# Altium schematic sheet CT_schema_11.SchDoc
size 564 x 458 mm
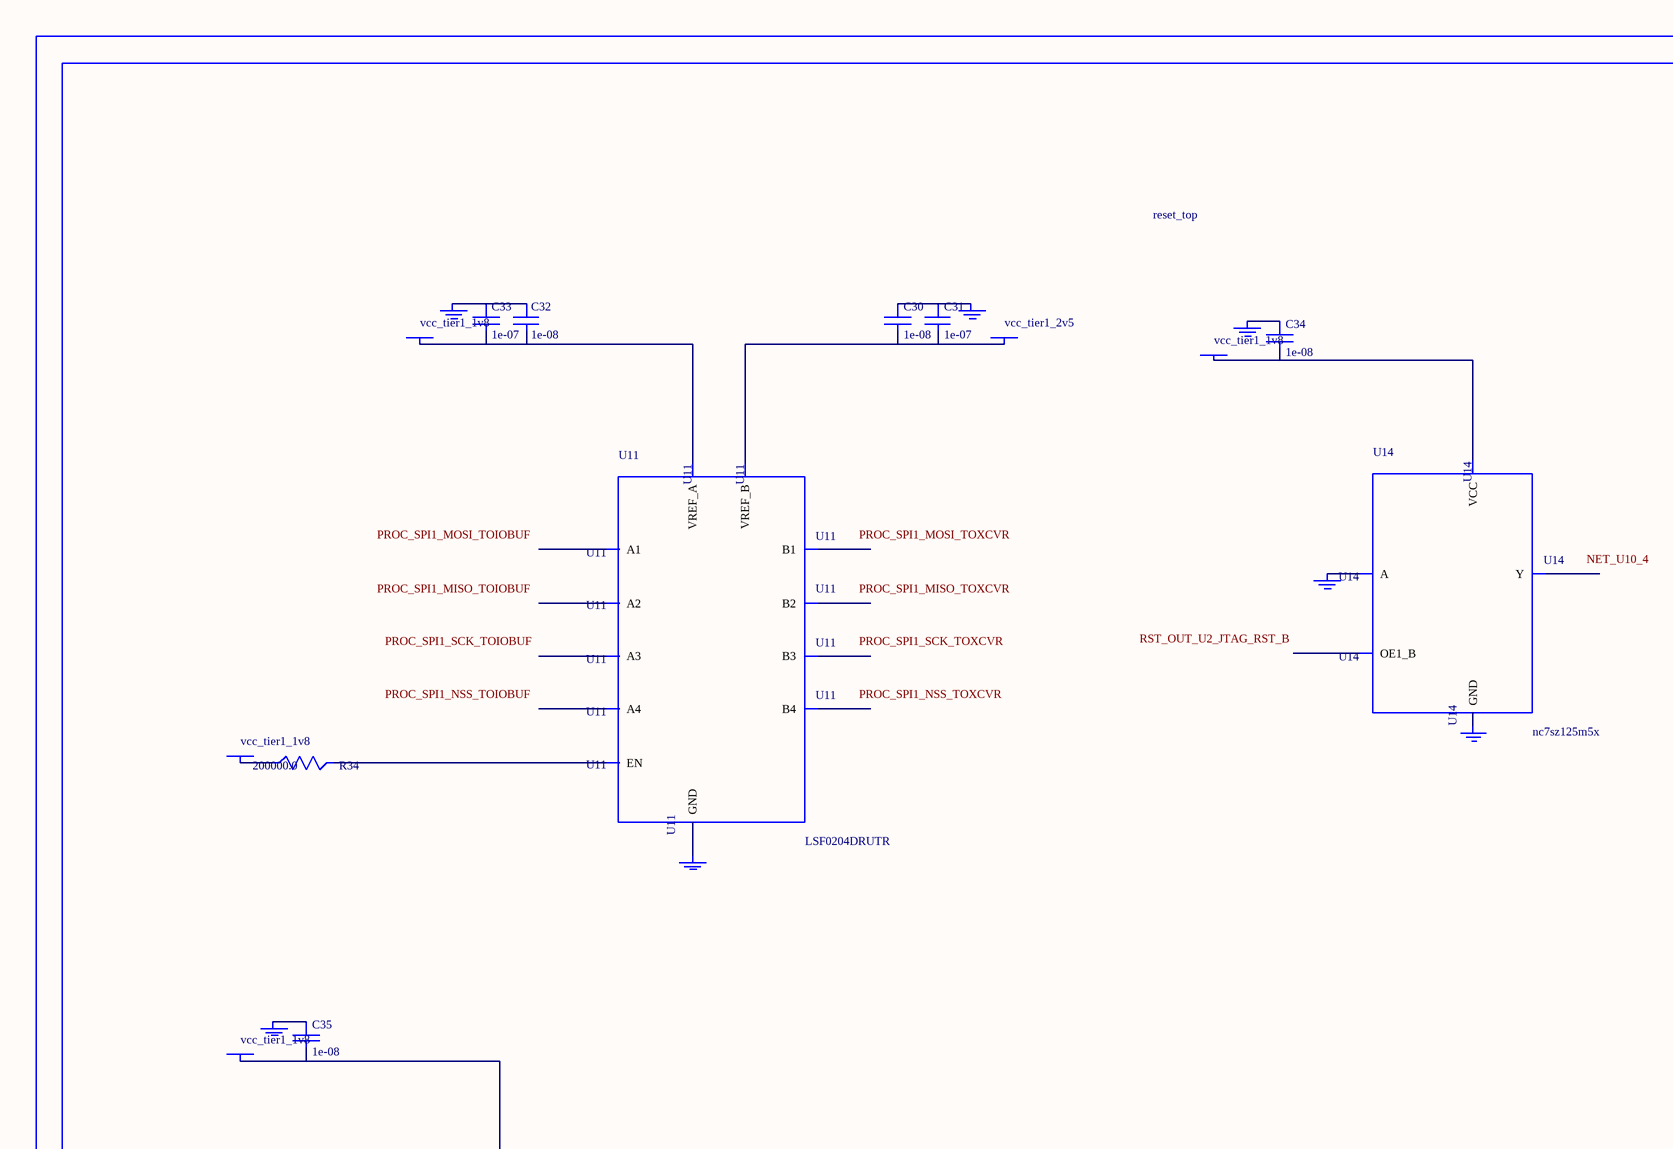
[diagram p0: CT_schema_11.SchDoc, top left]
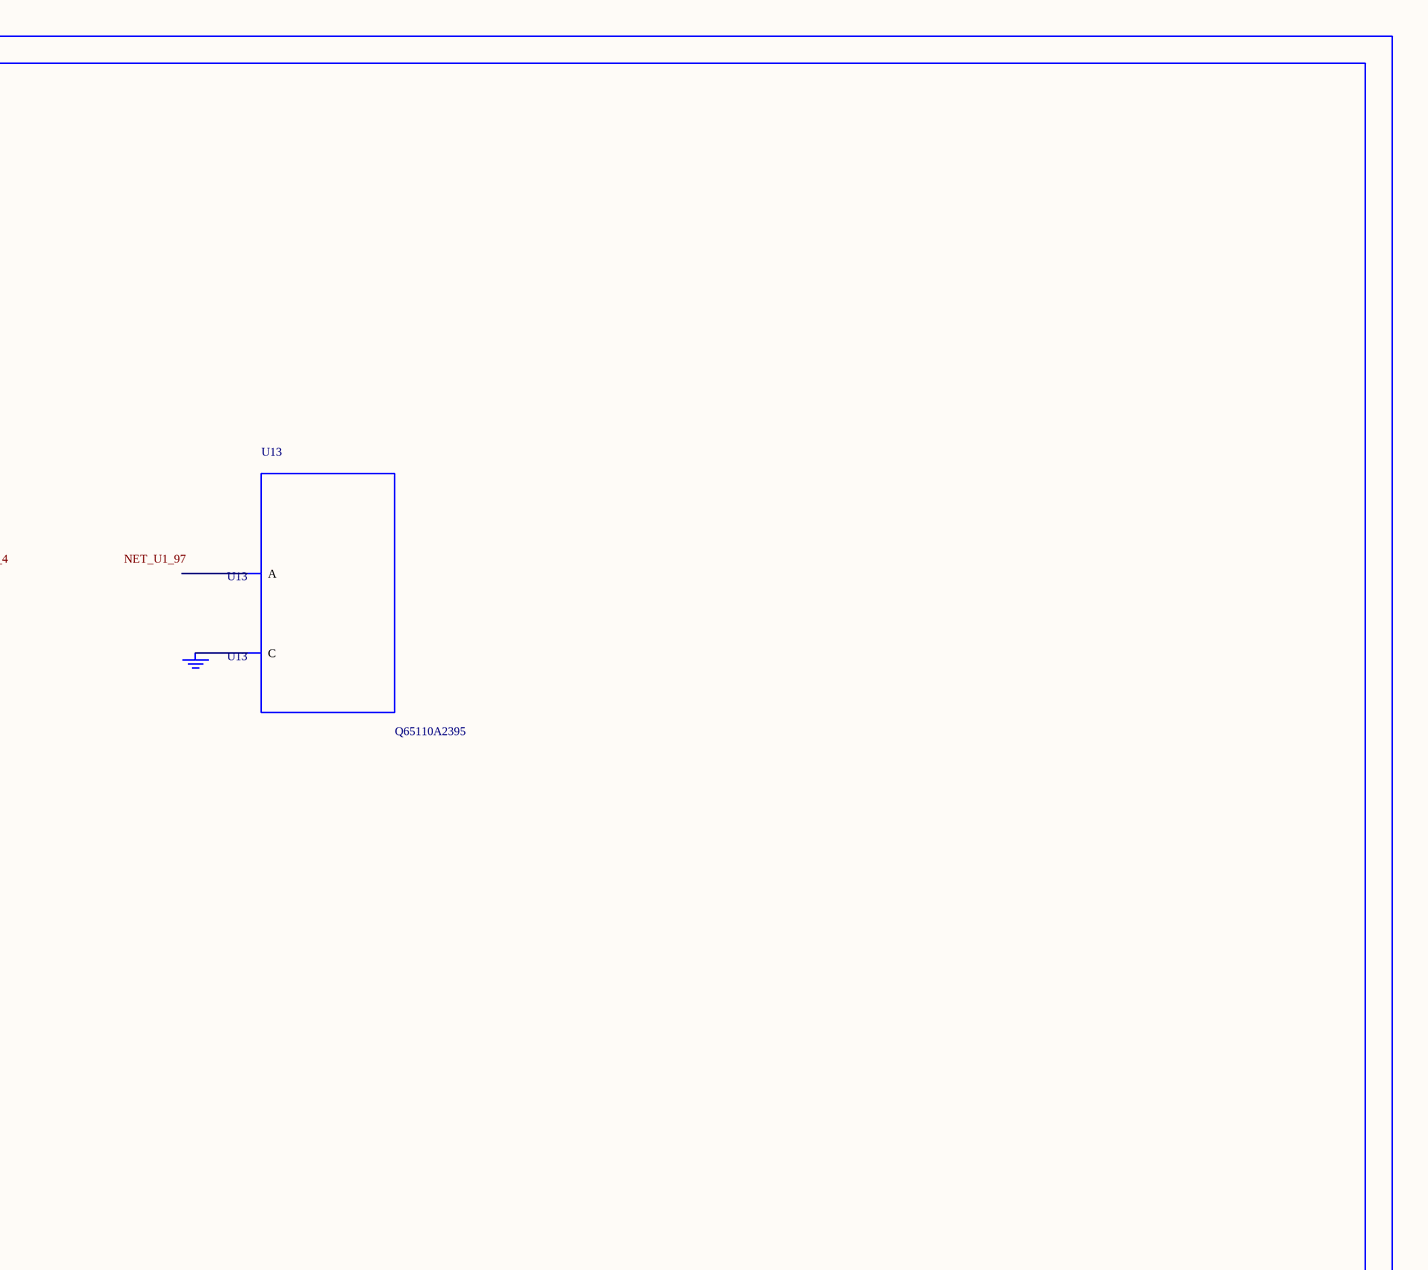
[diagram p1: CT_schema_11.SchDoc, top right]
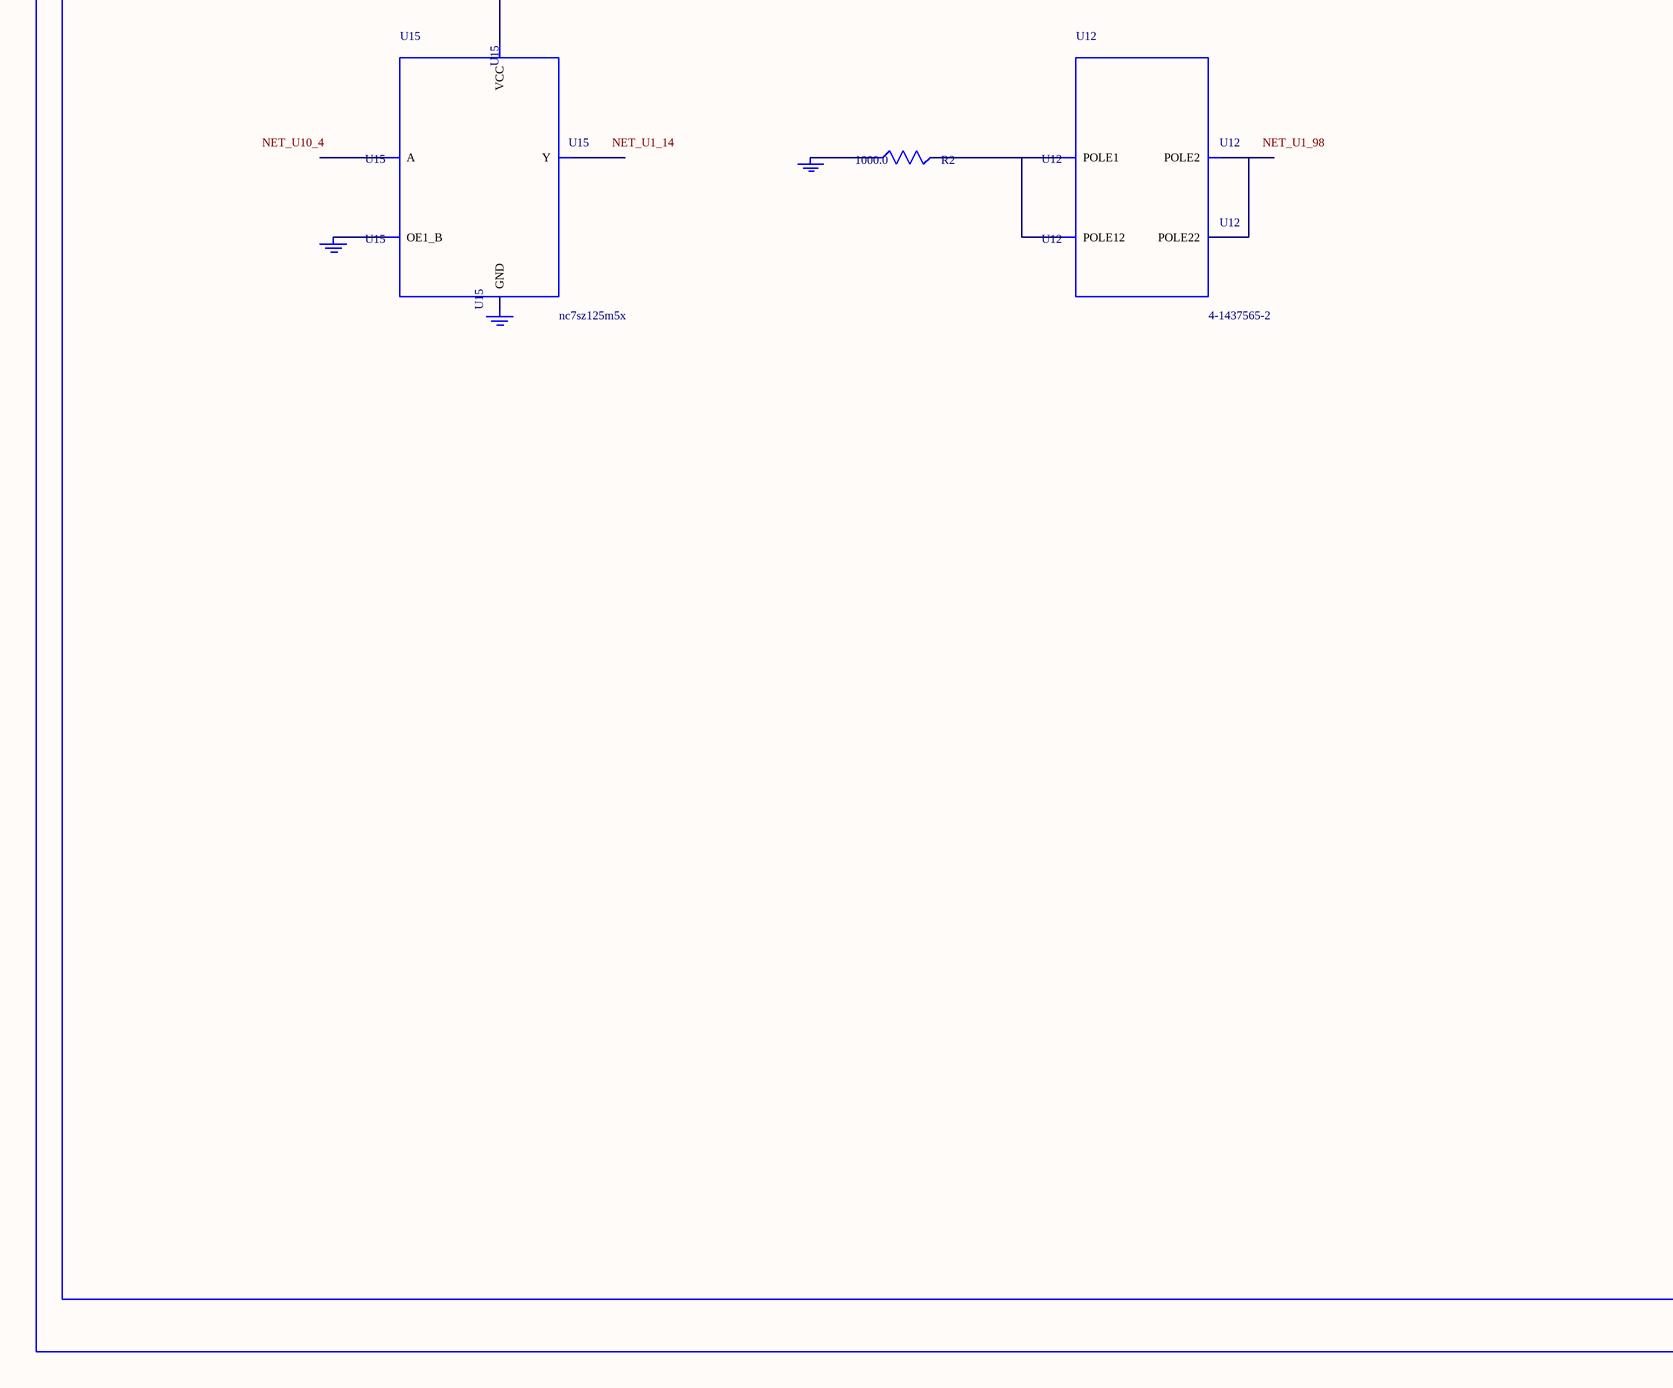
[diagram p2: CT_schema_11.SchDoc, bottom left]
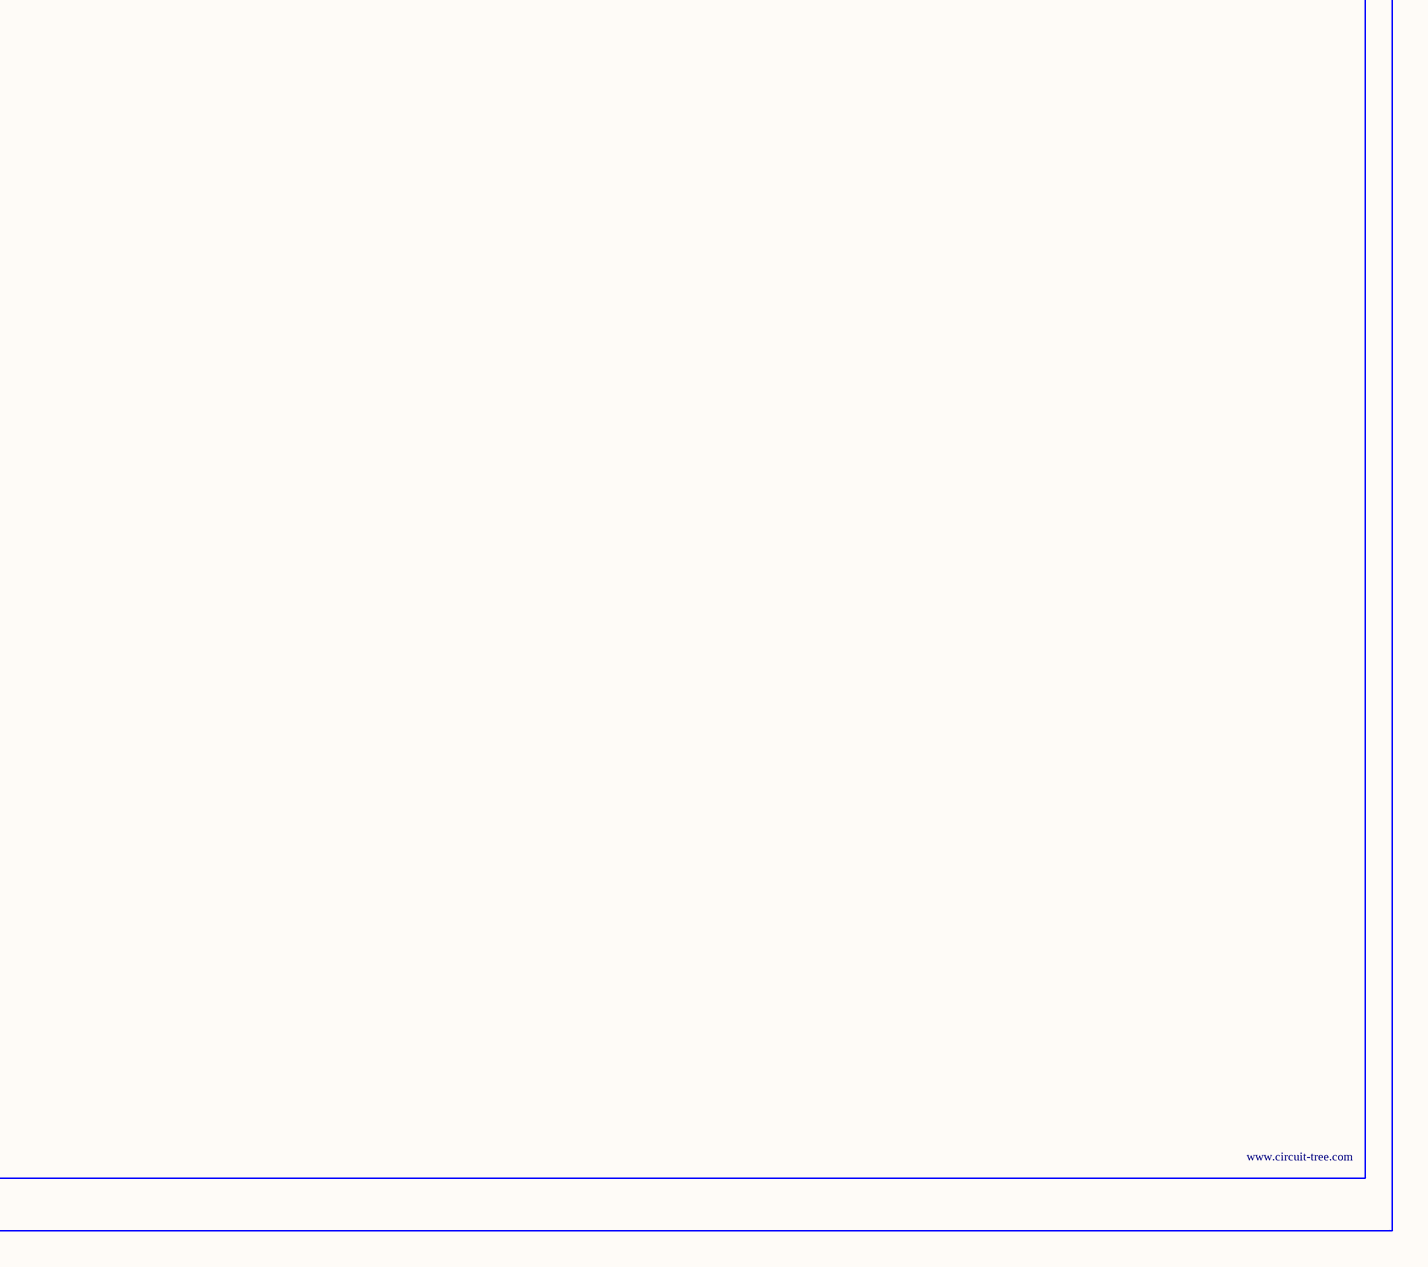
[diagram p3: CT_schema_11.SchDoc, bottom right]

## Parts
BORDER10  (no value)
C30  1e-08  [C0402]
C31  1e-07  [C0402]
C32  1e-08  [C0402]
C33  1e-07  [C0402]
C34  1e-08  [C0402]
C35  1e-08  [C0402]
GND_INSTANCE_10_0  (no value)
GND_INSTANCE_10_1  (no value)
GND_INSTANCE_10_2  (no value)
GND_INSTANCE_10_3  (no value)
GND_INSTANCE_10_4  (no value)
GND_INSTANCE_10_5  (no value)
GND_INSTANCE_10_6  (no value)
GND_INSTANCE_10_7  (no value)
GND_INSTANCE_10_8  (no value)
GND_INSTANCE_10_9  (no value)
GND_INSTANCE_10_10  (no value)
POWER_INSTANCE_10_0  vcc_tier1_1v8
POWER_INSTANCE_10_1  vcc_tier1_2v5
POWER_INSTANCE_10_2  vcc_tier1_1v8
POWER_INSTANCE_10_3  vcc_tier1_1v8
POWER_INSTANCE_10_4  vcc_tier1_1v8
R2  1000.0  [R0603]
R34  200000.0  [R0603]
U11  LSF0204DRUTR  [RUT0012A]
U12  4-1437565-2  [SW_4-1437565-2]
U13  Q65110A2395  [LGM67K-G1J2-24-Z]
U14  nc7sz125m5x  [NC7SZ125M5X]
U15  nc7sz125m5x  [NC7SZ125M5X]

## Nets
NetC30_1: C30.1 C31.1 GND_INSTANCE_10_1.0(GND)
NetC30_2: C30.2 C31.2 POWER_INSTANCE_10_1.0(PWR) U11.11(VREF_B)
NetC32_1: C32.1 C33.1 GND_INSTANCE_10_0.0(GND)
NetC32_2: C32.2 C33.2 POWER_INSTANCE_10_0.0(PWR) U11.1(VREF_A)
NetC34_1: C34.1 GND_INSTANCE_10_5.0(GND)
NetC34_2: C34.2 POWER_INSTANCE_10_3.0(PWR) U14.5(VCC)
NetC35_1: C35.1 GND_INSTANCE_10_8.0(GND)
NetC35_2: C35.2 POWER_INSTANCE_10_4.0(PWR) U15.5(VCC)
NetGND_INSTANCE_10_2_0: GND_INSTANCE_10_2.0(GND) U11.6(GND)
NetGND_INSTANCE_10_3_0: GND_INSTANCE_10_3.0(GND) R2.1
NetGND_INSTANCE_10_4_0: GND_INSTANCE_10_4.0(GND) U13.C
NetGND_INSTANCE_10_6_0: GND_INSTANCE_10_6.0(GND) U14.2(A)
NetGND_INSTANCE_10_7_0: GND_INSTANCE_10_7.0(GND) U14.3(GND)
NetGND_INSTANCE_10_9_0: GND_INSTANCE_10_9.0(GND) U15.1(OE1_B)
NetGND_INSTANCE_10_10_0: GND_INSTANCE_10_10.0(GND) U15.3(GND)
NetPOWER_INSTANCE_10_2_0: POWER_INSTANCE_10_2.0(PWR) R34.1
NetR2_2: R2.2 U12.1(POLE1) U12.2(POLE12)
NetR34_2: R34.2 U11.12(EN)
NetU12_3: U12.3(POLE2) U12.4(POLE22)

Not connected (* = marked no-connect by the designer): U11 2(A1) 3(A2) 4(A3) 5(A4) 7(B4) 8(B3) 9(B2) 10(B1); U13 A; U14 1(OE1_B) 4(Y); U15 2(A) 4(Y)

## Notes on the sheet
- Labels drawn without touching a wire or pin: NET_U1_14, NET_U1_97, NET_U1_98, NET_U10_4, PROC_SPI1_MISO_TOIOBUF, PROC_SPI1_MISO_TOXCVR, PROC_SPI1_MOSI_TOIOBUF, PROC_SPI1_MOSI_TOXCVR, PROC_SPI1_NSS_TOIOBUF, PROC_SPI1_NSS_TOXCVR, PROC_SPI1_SCK_TOIOBUF, PROC_SPI1_SCK_TOXCVR, RST_OUT_U2_JTAG_RST_B

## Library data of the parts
BORDER10 = BORDER_PAGE10
C30 C32 C34 C35 = C0402C103K3RAC
C31 C33 = C0402C104K3RACTU
GND_INSTANCE_10_0-GND_INSTANCE_10_10 = GND
POWER_INSTANCE_10_0-POWER_INSTANCE_10_4 = PWR
R2 = RC0603JR-071KL
R34 = RC0603JR-07200KL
